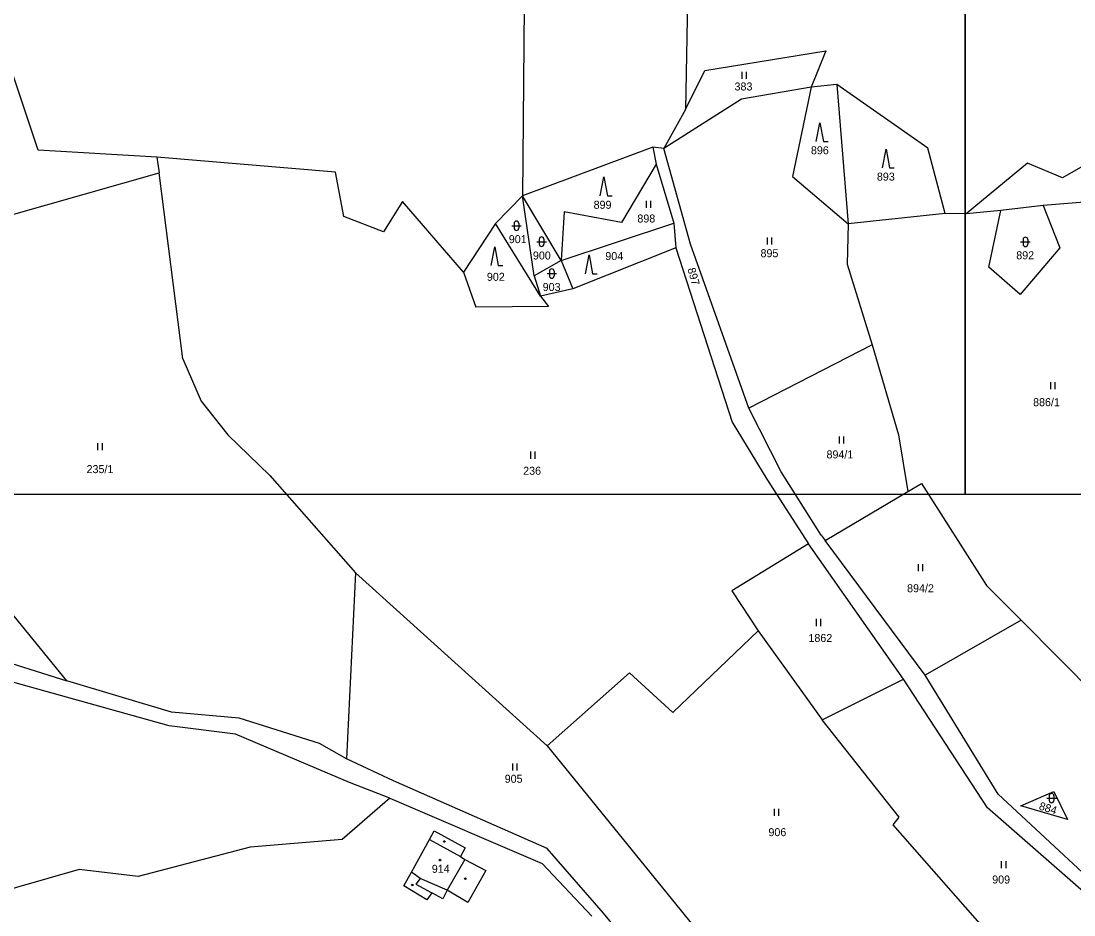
# Model space of a CAD drawing. Extents: x -670359 to -668019, y -978807 to -976674.
# Drawn here: x -669575.5 to -669351.9, y -977589.3 to -977399.4 of the extents above; entities that cross this region are included whole.
import ezdxf

# ---------------------------------------------------------------- set-up
doc = ezdxf.new("R2010")
doc.units = 0
for name, color, linetype in [('Hranice parcel', 7, 'Continuous'), ('ML1000', 7, 'Continuous'), ('Parcelní čísla', 7, 'Continuous'), ('Vnitřní kresba', 7, 'Continuous'), ('Značky budov', 7, 'Continuous'), ('Značky kultur', 7, 'Continuous')]:
    doc.layers.add(name, color=color, linetype=linetype)

msp = doc.modelspace()

# ---------------------------------------------------------------- linework, layer by layer
at = {"layer": 'Hranice parcel'}
for points in [[(-669432.31, -977302.48), (-669434.41, -977418.21)], [(-669467.87, -977307.57), (-669469.02, -977436.56)], [(-669571.83, -977426.86), (-669592.8, -977364.17)], [(-669430.29, -977409.95), (-669404.65, -977405.8)], [(-669404.65, -977405.8), (-669407.72, -977413.49)], [(-669434.41, -977418.21), (-669430.29, -977409.95)], [(-669407.72, -977413.49), (-669422.5, -977416.06)], [(-669407.72, -977413.49), (-669411.7, -977432.46)], [(-669402.29, -977412.9), (-669407.72, -977413.49)], [(-669402.29, -977412.9), (-669399.89, -977442.54)], [(-669382.94, -977426.45), (-669402.29, -977412.9)], [(-669422.5, -977416.06), (-669439, -977426.55)], [(-669434.41, -977418.21), (-669439, -977426.55)], [(-669546.63, -977428.39), (-669571.83, -977426.86)], [(-669441.32, -977426.24), (-669469.02, -977436.56)], [(-669441.32, -977426.24), (-669440.66, -977429.83)], [(-669439, -977426.55), (-669441.32, -977426.24)], [(-669433.37, -977446.81), (-669439, -977426.55)], [(-669379.27, -977440.34), (-669382.94, -977426.45)], [(-669546.63, -977428.39), (-669546.2, -977431.72)], [(-669508.71, -977431.52), (-669546.63, -977428.39)], [(-669347.1, -977428.56), (-669354.36, -977432.75)], [(-669506.98, -977440.94), (-669508.71, -977431.52)], [(-669440.66, -977429.83), (-669448.03, -977442.26)], [(-669440.66, -977429.83), (-669436.92, -977442.36)], [(-669361.81, -977429.6), (-669374.79, -977440.39)], [(-669354.36, -977432.75), (-669361.81, -977429.6)], [(-669609.96, -977449.78), (-669546.2, -977431.72)], [(-669541.12, -977471.19), (-669546.2, -977431.72)], [(-669411.7, -977432.46), (-669399.89, -977442.54)], [(-669324.35, -977435.85), (-669358.48, -977438.61)], [(-669494.52, -977437.75), (-669498.56, -977444.24)], [(-669481.56, -977452.77), (-669494.52, -977437.75)], [(-669469.02, -977436.56), (-669474.74, -977442.42)], [(-669460.78, -977450.33), (-669469.02, -977436.56)], [(-669466.52, -977453.56), (-669469.02, -977436.56)], [(-669460.2, -977439.94), (-669460.78, -977450.33)], [(-669448.03, -977442.26), (-669460.2, -977439.94)], [(-669379.27, -977440.34), (-669399.89, -977442.54)], [(-669374.79, -977440.39), (-669379.27, -977440.34)], [(-669367.44, -977439.71), (-669374.79, -977440.39)], [(-669370.01, -977451.71), (-669367.44, -977439.71)], [(-669358.48, -977438.61), (-669367.44, -977439.71)], [(-669358.48, -977438.61), (-669354.92, -977447.62)], [(-669498.56, -977444.24), (-669506.98, -977440.94)], [(-669474.74, -977442.42), (-669481.56, -977452.77)], [(-669465.22, -977457.87), (-669474.74, -977442.42)], [(-669460.78, -977450.33), (-669436.92, -977442.36)], [(-669436.92, -977442.36), (-669436.49, -977447.63)], [(-669399.89, -977442.54), (-669400.08, -977451.09)], [(-669420.95, -977481.66), (-669433.37, -977446.81)], [(-669436.49, -977447.63), (-669458.35, -977456.31)], [(-669436.49, -977447.63), (-669424.53, -977484.64)], [(-669354.92, -977447.62), (-669363.34, -977457.5)], [(-669460.78, -977450.33), (-669466.52, -977453.56)], [(-669460.78, -977450.33), (-669458.35, -977456.31)], [(-669400.08, -977451.09), (-669394.79, -977468.24)], [(-669363.34, -977457.5), (-669370.01, -977451.71)], [(-669481.56, -977452.77), (-669478.96, -977460.19)], [(-669466.52, -977453.56), (-669465.22, -977457.87)], [(-669458.35, -977456.31), (-669465.22, -977457.87)], [(-669465.22, -977457.87), (-669463.53, -977460.1)], [(-669463.53, -977460.1), (-669478.96, -977460.19)], [(-669394.79, -977468.24), (-669420.95, -977481.66)], [(-669394.79, -977468.24), (-669389.17, -977487.38)], [(-669541.12, -977471.19), (-669537.23, -977480.19)], [(-669537.23, -977480.19), (-669531.6, -977487.35)], [(-669414.08, -977495.2), (-669420.95, -977481.66)], [(-669424.53, -977484.64), (-669417.11, -977496.74)], [(-669531.6, -977487.35), (-669522.67, -977496.01)], [(-669389.17, -977487.38), (-669387.17, -977499.38)], [(-669522.67, -977496.01), (-669504.49, -977516.68)], [(-669405.61, -977508.66), (-669414.08, -977495.2)], [(-669417.11, -977496.74), (-669408.32, -977510.51)], [(-669387.17, -977499.38), (-669384.3, -977497.68)], [(-669384.3, -977497.68), (-669370.53, -977519.34)], [(-669404.75, -977509.82), (-669387.17, -977499.38)], [(-669405.61, -977508.66), (-669404.75, -977509.82)], [(-669383.54, -977538.41), (-669404.75, -977509.82)], [(-669408.32, -977510.51), (-669424.58, -977520.52)], [(-669388.09, -977539.24), (-669408.32, -977510.51)], [(-669504.49, -977516.68), (-669506.36, -977556.17)], [(-669463.75, -977553.44), (-669504.49, -977516.68)], [(-669565.78, -977539.58), (-669582.61, -977518.98)], [(-669424.58, -977520.52), (-669419.01, -977528.96)], [(-669370.53, -977519.34), (-669363.13, -977526.7)], [(-669363.13, -977526.7), (-669383.54, -977538.41)], [(-669363.13, -977526.7), (-669347.06, -977542.92)], [(-669419.01, -977528.96), (-669437.07, -977546.32)], [(-669419.01, -977528.96), (-669405.4, -977547.89)], [(-669585.57, -977533.39), (-669565.78, -977539.58)], [(-669544.06, -977549.2), (-669585.95, -977537.46)], [(-669446.32, -977537.91), (-669463.75, -977553.44)], [(-669437.07, -977546.32), (-669446.32, -977537.91)], [(-669368.05, -977563.65), (-669383.54, -977538.41)], [(-669543.52, -977546.24), (-669565.78, -977539.58)], [(-669405.4, -977547.89), (-669388.09, -977539.24)], [(-669370.27, -977566.62), (-669388.09, -977539.24)], [(-669529.19, -977547.51), (-669543.52, -977546.24)], [(-669512.13, -977552.93), (-669529.19, -977547.51)], [(-669389.05, -977568.57), (-669405.4, -977547.89)], [(-669529.98, -977550.95), (-669544.06, -977549.2)], [(-669505.77, -977561.2), (-669529.98, -977550.95)], [(-669506.36, -977556.17), (-669512.13, -977552.93)], [(-669463.75, -977553.44), (-669432.59, -977591.85)], [(-669496.41, -977560.82), (-669506.36, -977556.17)], [(-669497.19, -977564.5), (-669505.77, -977561.2)], [(-669463.79, -977575.25), (-669496.41, -977560.82)], [(-669363.23, -977566.18), (-669356.21, -977563.1)], [(-669356.21, -977563.1), (-669353.3, -977569.08)], [(-669497.19, -977564.5), (-669507.3, -977573.35)], [(-669497.19, -977564.5), (-669464.81, -977578.38)], [(-669341.12, -977588.67), (-669368.05, -977563.65)], [(-669343.11, -977590.36), (-669370.27, -977566.62)], [(-669353.3, -977569.08), (-669363.23, -977566.18)], [(-669390.32, -977570.18), (-669389.05, -977568.57)], [(-669368.28, -977595.3), (-669390.32, -977570.18)], [(-669488.75, -977573.32), (-669487.75, -977571.48)], [(-669487.75, -977571.48), (-669481.16, -977575.07)], [(-669507.3, -977573.35), (-669526.81, -977574.91)], [(-669492.6, -977580.25), (-669488.75, -977573.32)], [(-669526.81, -977574.91), (-669550.6, -977581.2)], [(-669481.16, -977575.07), (-669482.16, -977576.91)], [(-669482.16, -977576.91), (-669481.3, -977577.55)], [(-669451.8, -977588.93), (-669463.79, -977575.25)], [(-669481.3, -977577.55), (-669476.8, -977579.89)], [(-669464.81, -977578.38), (-669454.27, -977589.58)], [(-669563.17, -977579.68), (-669596.46, -977589.23)], [(-669550.6, -977581.2), (-669563.17, -977579.68)], [(-669494.21, -977583.19), (-669492.6, -977580.25)], [(-669476.8, -977579.89), (-669480.6, -977586.7)], [(-669489.32, -977586.11), (-669494.21, -977583.19)], [(-669488.29, -977584.65), (-669489.32, -977586.11)], [(-669485.96, -977585.95), (-669488.29, -977584.65)], [(-669485, -977584.09), (-669485.96, -977585.95)], [(-669480.6, -977586.7), (-669485, -977584.09)], [(-669443.43, -977599.18), (-669451.8, -977588.93)]]:
    msp.add_lwpolyline(points, dxfattribs=at)
at = {"layer": 'ML1000'}
for points in [[(-669375, -977000), (-669375, -977500), (-670000, -977500), (-670000, -977000)], [(-668750, -977000), (-668750, -977500), (-669375, -977500), (-669375, -977000)]]:
    msp.add_lwpolyline(points, close=True, dxfattribs=at)
at = {"layer": 'Vnitřní kresba'}
for points in [[(-669488.75, -977573.32), (-669482.16, -977576.91)], [(-669481.3, -977577.55), (-669485, -977584.09)], [(-669490.75, -977581.6), (-669492.6, -977580.25)], [(-669490.75, -977581.6), (-669491.64, -977582.77)], [(-669491.64, -977582.77), (-669488.29, -977584.65)], [(-669485, -977584.09), (-669490.75, -977581.6)]]:
    msp.add_lwpolyline(points, dxfattribs=at)
at = {"layer": 'Značky budov'}
msp.add_circle((-669486.52, -977577.69), 0.175, dxfattribs=at)
at = {"layer": 'Značky kultur'}
for p, q in [((-669422.45, -977410.24), (-669422.45, -977411.74)), ((-669421.45, -977411.74), (-669421.45, -977410.24)), ((-669442.75, -977437.6), (-669442.75, -977439.1)), ((-669441.75, -977439.1), (-669441.75, -977437.6)), ((-669470.82, -977442.42), (-669470.82, -977443.42)), ((-669469.82, -977442.42), (-669469.82, -977443.42)), ((-669471.32, -977442.92), (-669469.32, -977442.92)), ((-669465.96, -977446.31), (-669463.96, -977446.31)), ((-669465.46, -977445.81), (-669465.46, -977446.81)), ((-669464.46, -977445.81), (-669464.46, -977446.81)), ((-669417.05, -977445.41), (-669417.05, -977446.91)), ((-669416.05, -977446.91), (-669416.05, -977445.41)), ((-669363.25, -977446.35), (-669361.25, -977446.35)), ((-669362.75, -977445.85), (-669362.75, -977446.85)), ((-669361.75, -977445.85), (-669361.75, -977446.85)), ((-669463.8, -977453.09), (-669461.8, -977453.09)), ((-669463.3, -977452.59), (-669463.3, -977453.59)), ((-669462.3, -977452.59), (-669462.3, -977453.59)), ((-669356.94, -977476.17), (-669356.94, -977477.67)), ((-669355.94, -977477.67), (-669355.94, -977476.17)), ((-669559.23, -977489.13), (-669559.23, -977490.63)), ((-669558.23, -977490.63), (-669558.23, -977489.13)), ((-669401.76, -977487.71), (-669401.76, -977489.21)), ((-669400.76, -977489.21), (-669400.76, -977487.71)), ((-669467.31, -977490.91), (-669467.31, -977492.41)), ((-669466.31, -977492.41), (-669466.31, -977490.91)), ((-669385.03, -977514.83), (-669385.03, -977516.33)), ((-669384.03, -977516.33), (-669384.03, -977514.83)), ((-669406.67, -977526.47), (-669406.67, -977527.97)), ((-669405.67, -977527.97), (-669405.67, -977526.47)), ((-669471.12, -977557.14), (-669471.12, -977558.64)), ((-669470.12, -977558.64), (-669470.12, -977557.14)), ((-669357.67, -977564.51), (-669355.67, -977564.51)), ((-669357.17, -977564.01), (-669357.17, -977565.01)), ((-669356.17, -977564.01), (-669356.17, -977565.01)), ((-669415.59, -977566.79), (-669415.59, -977568.29)), ((-669414.59, -977568.29), (-669414.59, -977566.79)), ((-669367.36, -977577.92), (-669367.36, -977579.42)), ((-669366.36, -977579.42), (-669366.36, -977577.92))]:
    msp.add_line(p, q, dxfattribs=at)
for points in [[(-669406.64, -977425.05), (-669405.89, -977421.05), (-669405.14, -977425.05), (-669404.14, -977425.05)], [(-669392.59, -977430.64), (-669391.84, -977426.64), (-669391.09, -977430.64), (-669390.09, -977430.64)], [(-669452.5, -977436.54), (-669451.75, -977432.54), (-669451, -977436.54), (-669450, -977436.54)], [(-669475.67, -977451.4), (-669474.92, -977447.4), (-669474.17, -977451.4), (-669473.17, -977451.4)], [(-669455.65, -977453.14), (-669454.9, -977449.14), (-669454.15, -977453.14), (-669453.15, -977453.14)]]:
    msp.add_lwpolyline(points, dxfattribs=at)
for centre in [(-669485.61, -977573.74), (-669486.52, -977577.69), (-669492.42, -977582.97), (-669481.15, -977581.64)]:
    msp.add_circle(centre, 0.175, dxfattribs=at)
for centre, start, end in [((-669470.32, -977442.42), 0, 180), ((-669470.32, -977443.42), 180, 0), ((-669464.96, -977445.81), 0, 180), ((-669464.96, -977446.81), 180, 0), ((-669362.25, -977445.85), 0, 180), ((-669362.25, -977446.85), 180, 0), ((-669462.8, -977452.59), 0, 180), ((-669462.8, -977453.59), 180, 0), ((-669356.67, -977564.01), 0, 180), ((-669356.67, -977565.01), 180, 0)]:
    msp.add_arc(centre, 0.5, start, end, dxfattribs=at)

# ---------------------------------------------------------------- texts
at = {"layer": 'Parcelní čísla'}
for s, p in [('383', (-669424, -977414.19)), ('896', (-669407.78, -977427.75)), ('893', (-669393.77, -977433.34)), ('899', (-669453.92, -977439.32)), ('898', (-669444.63, -977442.24)), ('901', (-669471.93, -977446.62)), ('900', (-669466.81, -977450.1)), ('904', (-669451.43, -977450.22)), ('895', (-669418.48, -977449.61)), ('892', (-669364.18, -977450.05)), ('902', (-669476.58, -977454.63)), ('903', (-669464.73, -977456.79)), ('886/1', (-669360.61, -977481.26)), ('894/1', (-669404.47, -977492.36)), ('235/1', (-669561.58, -977495.48)), ('236', (-669468.88, -977495.83)), ('894/2', (-669387.36, -977520.79)), ('1862', (-669408.31, -977531.36)), ('905', (-669472.8, -977561.26)), ('906', (-669416.8, -977572.6)), ('914', (-669488.28, -977580.39)), ('909', (-669369.29, -977582.66))]:
    msp.add_text(s, height=1.7, dxfattribs=at).set_placement(p)
for s, rotation, p in [('897', 285.7646, (-669434.02, -977452.11)), ('884', 342.8014, (-669359.49, -977566.91))]:
    msp.add_text(s, height=1.7, rotation=rotation, dxfattribs=at).set_placement(p)

doc.saveas('drawing.dxf')
